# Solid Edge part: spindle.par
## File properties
Author: jmrobins
Template: ANSIMM.PAR
Last saved by: rkriggs
Revision: 50
Application: Solid Edge
Density: 0.000008027 kg/mm^3
Accuracy: 0.99
Material: Stainless Steel, 304
Face Style: Steel
Fill Style: ANSI32(Steel)
Virtual Style: Stainless steel
Coef. of Thermal Exp: 1.7e-05
Thermal Conductivity: 17.0
Specific Heat: 502.0
Modulus of Elasticity: 193053196000.0
Poission's Ratio: 0.29
Yield Stress: 255106009.0
Ultimate Stress: 579159588.0
Elongation: 0.0
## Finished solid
Body 1: solid body, 17 faces, 34 edges, 20 vertices.
  Faces by surface: plane 12, cylinder 3, cone 2
  Edges by curve: line 16, circle 14, intersection 4
Bounding box of the edges (mm): 20.000 x 20.000 x 107.000, from (-10, -10, 0) to (10, 10, 107).
Cylindrical faces by radius (mm): R7.5 x2, R10 x1
Conical faces (half-angle, radius in mm at the cone's reference point): 45 deg R7.5 x2
Planar faces by outward normal: +x 1, +y 1, +z 4, -x 1, -y 1, -z 4
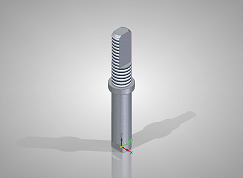
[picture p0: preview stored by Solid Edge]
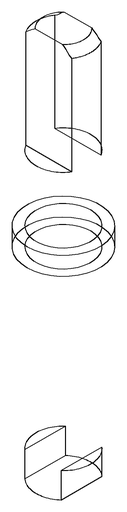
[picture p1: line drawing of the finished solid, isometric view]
